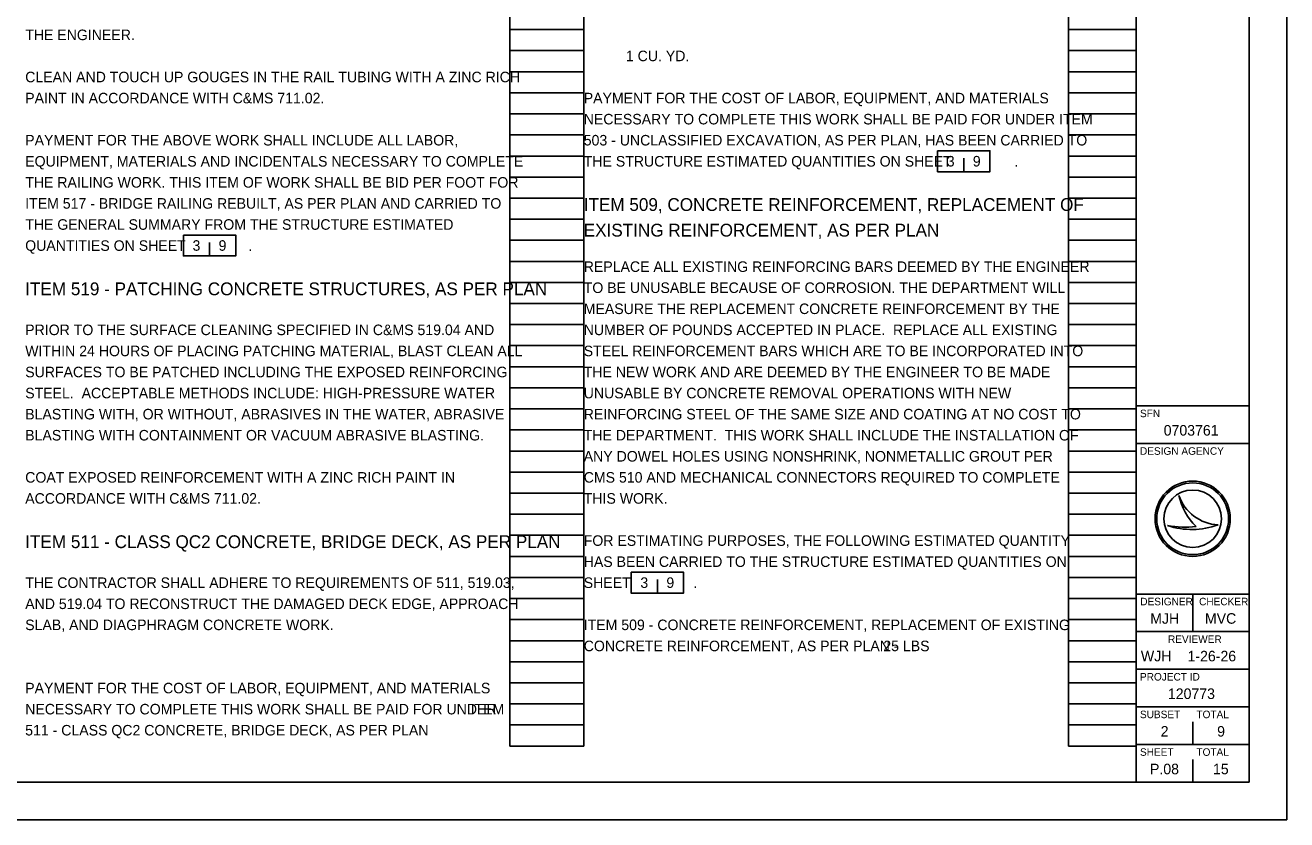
# Model space of a CAD drawing. Extents: x -16.5 to 61.9, y -20 to 22.7.
# Drawn here: x 17.24 to 34, y 0 to 10.56 of the extents above; entities that cross this region are included whole.
import ezdxf

# ---------------------------------------------------------------- set-up
doc = ezdxf.new("R2010")
doc.units = 0
for name, color, linetype in [('SH_Border', 7, 'Continuous'), ('SH_Cut_Line', 7, 'Continuous'), ('SH_Data', 7, 'Continuous'), ('SH_Text', 7, 'Continuous')]:
    doc.layers.add(name, color=color, linetype=linetype)

msp = doc.modelspace()

# ---------------------------------------------------------------- linework, layer by layer
at = {"layer": 'SH_Border'}
for p, q in [((32, 0.5), (32, 21.5)), ((32, 5.5), (33.5, 5.5)), ((32, 5), (33.5, 5)), ((32, 3), (33.5, 3)), ((32.75, 3), (32.75, 2.5)), ((32, 2.5), (33.5, 2.5)), ((32, 2), (33.5, 2)), ((32, 1.5), (33.5, 1.5)), ((32, 1), (33.5, 1))]:
    msp.add_line(p, q, dxfattribs=at)
msp.add_lwpolyline([(1.5, 21.5), (33.5, 21.5), (33.5, 0.5), (1.5, 0.5)], close=True, dxfattribs=at)
at = {"layer": 'SH_Cut_Line'}
msp.add_lwpolyline([(0, 0), (34, 0), (34, 22), (0, 22)], close=True, dxfattribs=at)
at = {"layer": 'SH_Data'}
for p, q in [((23.68, 0.98), (23.68, 21.14)), ((24.66, 0.98), (24.66, 21.14)), ((31.1, 0.98), (31.1, 21.14)), ((32, 0.98), (32, 21.14)), ((23.68, 10.5), (24.66, 10.5)), ((31.1, 10.5), (32, 10.5)), ((23.68, 10.22), (24.66, 10.22)), ((31.1, 10.22), (32, 10.22)), ((23.68, 9.94), (24.66, 9.94)), ((31.1, 9.94), (32, 9.94)), ((23.68, 9.66), (24.66, 9.66)), ((31.1, 9.66), (32, 9.66)), ((23.68, 9.38), (24.66, 9.38)), ((31.1, 9.38), (32, 9.38)), ((23.68, 9.1), (24.66, 9.1)), ((31.1, 9.1), (32, 9.1)), ((23.68, 8.82), (24.66, 8.82)), ((31.1, 8.82), (32, 8.82)), ((23.68, 8.54), (24.66, 8.54)), ((31.1, 8.54), (32, 8.54)), ((23.68, 8.26), (24.66, 8.26)), ((31.1, 8.26), (32, 8.26)), ((23.68, 7.98), (24.66, 7.98)), ((31.1, 7.98), (32, 7.98)), ((23.68, 7.7), (24.66, 7.7)), ((31.1, 7.7), (32, 7.7)), ((23.68, 7.42), (24.66, 7.42)), ((31.1, 7.42), (32, 7.42)), ((23.68, 7.14), (24.66, 7.14)), ((31.1, 7.14), (32, 7.14)), ((23.68, 6.86), (24.66, 6.86)), ((31.1, 6.86), (32, 6.86)), ((23.68, 6.58), (24.66, 6.58)), ((31.1, 6.58), (32, 6.58)), ((23.68, 6.3), (24.66, 6.3)), ((31.1, 6.3), (32, 6.3)), ((23.68, 6.02), (24.66, 6.02)), ((31.1, 6.02), (32, 6.02)), ((23.68, 5.74), (24.66, 5.74)), ((31.1, 5.74), (32, 5.74)), ((23.68, 5.46), (24.66, 5.46)), ((31.1, 5.46), (32, 5.46)), ((23.68, 5.18), (24.66, 5.18)), ((31.1, 5.18), (32, 5.18)), ((23.68, 4.9), (24.66, 4.9)), ((31.1, 4.9), (32, 4.9)), ((23.68, 4.62), (24.66, 4.62)), ((31.1, 4.62), (32, 4.62)), ((23.68, 4.34), (24.66, 4.34)), ((31.1, 4.34), (32, 4.34)), ((32.567, 4.31), (32.567, 4.31)), ((23.68, 4.06), (24.66, 4.06)), ((31.1, 4.06), (32, 4.06)), ((32.417, 3.91), (32.417, 3.91)), ((32.75, 4), (32.75, 4)), ((33.087, 3.919), (33.087, 3.919)), ((23.68, 3.78), (24.66, 3.78)), ((31.1, 3.78), (32, 3.78)), ((23.68, 3.5), (24.66, 3.5)), ((31.1, 3.5), (32, 3.5)), ((23.68, 3.22), (24.66, 3.22)), ((31.1, 3.22), (32, 3.22)), ((23.68, 2.94), (24.66, 2.94)), ((31.1, 2.94), (32, 2.94)), ((23.68, 2.66), (24.66, 2.66)), ((31.1, 2.66), (32, 2.66)), ((23.68, 2.38), (24.66, 2.38)), ((31.1, 2.38), (32, 2.38)), ((23.68, 2.1), (24.66, 2.1)), ((31.1, 2.1), (32, 2.1)), ((23.68, 1.82), (24.66, 1.82)), ((31.1, 1.82), (32, 1.82)), ((23.68, 1.54), (24.66, 1.54)), ((31.1, 1.54), (32, 1.54)), ((23.68, 1.26), (24.66, 1.26)), ((31.1, 1.26), (32, 1.26)), ((32.75, 1), (32.75, 1.3)), ((23.68, 0.98), (24.66, 0.98)), ((31.1, 0.98), (32, 0.98)), ((32.375, 0.675), (32.375, 0.675)), ((32.75, 0.5), (32.75, 0.8))]:
    msp.add_line(p, q, dxfattribs=at)
for radius in [0.5, 0.477, 0.477, 0.382]:
    msp.add_circle((32.75, 4), radius, dxfattribs=at)
for centre, radius, start, end in [((33.116, 4.498), 0.58, 198.9257, 198.9319), ((33.347, 4.47), 0.796, 191.6379, 191.6421), ((33.116, 4.498), 0.58, 198.9319, 267.1657), ((33.347, 4.47), 0.796, 191.6421, 226.0947), ((32.739, 4.87), 1.013, 251.4576, 290.0832), ((32.648, 5.154), 1.266, 259.4964, 259.4995), ((32.739, 4.87), 1.013, 251.4527, 251.4576), ((32.648, 5.154), 1.266, 259.4995, 276.6672)]:
    msp.add_arc(centre, radius, start, end, dxfattribs=at)
at = {"layer": 'SH_Text'}
for p, q in [((29.709, 8.792), (29.709, 8.612)), ((19.689, 7.672), (19.689, 7.492)), ((25.638, 3.192), (25.638, 3.012))]:
    msp.add_line(p, q, dxfattribs=at)
for points in [[(29.361, 8.89), (30.057, 8.89), (30.057, 8.612), (29.361, 8.612)], [(19.341, 7.77), (20.037, 7.77), (20.037, 7.492), (19.341, 7.492)], [(25.29, 3.29), (25.986, 3.29), (25.986, 3.012), (25.29, 3.012)]]:
    msp.add_lwpolyline(points, close=True, dxfattribs=at)

# ---------------------------------------------------------------- texts
at = {"layer": 'SH_Data'}
for s, p in [('3', (29.483, 8.681)), ('9', (29.829, 8.681)), ('3', (19.463, 7.561)), ('9', (19.809, 7.561)), ('3', (25.412, 3.081)), ('9', (25.758, 3.081))]:
    msp.add_text(s, height=0.14, rotation=0, dxfattribs=at).set_placement(p)
for s, height, p in [('SFN', 0.1, (32.05, 5.35)), ('0703761', 0.14, (32.365, 5.105)), ('DESIGN AGENCY', 0.1, (32.05, 4.85)), ('DESIGNER', 0.1, (32.054, 2.85)), ('CHECKER', 0.1, (32.835, 2.85)), ('MJH', 0.14, (32.186, 2.605)), ('MVC', 0.14, (32.913, 2.605)), ('REVIEWER', 0.1, (32.422, 2.35)), ('WJH', 0.14, (32.062, 2.105)), ('1-26-26', 0.14, (32.682, 2.105)), ('PROJECT ID', 0.1, (32.05, 1.85)), ('120773', 0.14, (32.421, 1.605)), ('SUBSET', 0.1, (32.05, 1.35)), ('TOTAL', 0.1, (32.8, 1.35)), ('2', 0.14, (32.325, 1.105)), ('9', 0.14, (33.075, 1.105)), ('SHEET', 0.1, (32.05, 0.85)), ('TOTAL', 0.1, (32.8, 0.85)), ('P.08', 0.14, (32.183, 0.605)), ('15', 0.14, (33.02, 0.605))]:
    msp.add_text(s, height=height, dxfattribs=at).set_placement(p)
at = {"layer": 'SH_Text'}
for s, height, p in [('THE ENGINEER.', 0.14, (17.24, 10.36)), ('1 CU. YD. ', 0.14, (25.22, 10.08)), ('CLEAN AND TOUCH UP GOUGES IN THE RAIL TUBING WITH A ZINC RICH ', 0.14, (17.24, 9.8)), ('PAINT IN ACCORDANCE WITH C&MS 711.02.', 0.14, (17.24, 9.52)), ('PAYMENT FOR THE COST OF LABOR, EQUIPMENT, AND MATERIALS ', 0.14, (24.66, 9.52)), ('NECESSARY TO COMPLETE THIS WORK SHALL BE PAID FOR UNDER ITEM ', 0.14, (24.66, 9.24)), ('PAYMENT FOR THE ABOVE WORK SHALL INCLUDE ALL LABOR, ', 0.14, (17.24, 8.96)), ('503 - UNCLASSIFIED EXCAVATION, AS PER PLAN, HAS BEEN CARRIED TO ', 0.14, (24.66, 8.96)), ('EQUIPMENT, MATERIALS AND INCIDENTALS NECESSARY TO COMPLETE ', 0.14, (17.24, 8.68)), ('THE STRUCTURE ESTIMATED QUANTITIES ON SHEET                .', 0.14, (24.66, 8.68)), ('THE RAILING WORK. THIS ITEM OF WORK SHALL BE BID PER FOOT FOR ', 0.14, (17.24, 8.4)), ('ITEM 517 - BRIDGE RAILING REBUILT, AS PER PLAN AND CARRIED TO ', 0.14, (17.24, 8.12)), ('ITEM 509, CONCRETE REINFORCEMENT, REPLACEMENT OF ', 0.17, (24.66, 8.09)), ('THE GENERAL SUMMARY FROM THE STRUCTURE ESTIMATED ', 0.14, (17.24, 7.84)), ('EXISTING REINFORCEMENT, AS PER PLAN', 0.17, (24.66, 7.75)), ('QUANTITIES ON SHEET                .', 0.14, (17.24, 7.56)), ('REPLACE ALL EXISTING REINFORCING BARS DEEMED BY THE ENGINEER ', 0.14, (24.66, 7.28)), ('ITEM 519 - PATCHING CONCRETE STRUCTURES, AS PER PLAN', 0.17, (17.24, 6.97)), ('TO BE UNUSABLE BECAUSE OF CORROSION. THE DEPARTMENT WILL ', 0.14, (24.66, 7)), ('MEASURE THE REPLACEMENT CONCRETE REINFORCEMENT BY THE ', 0.14, (24.66, 6.72)), ('PRIOR TO THE SURFACE CLEANING SPECIFIED IN C&MS 519.04 AND ', 0.14, (17.24, 6.44)), ('NUMBER OF POUNDS ACCEPTED IN PLACE.  REPLACE ALL EXISTING ', 0.14, (24.66, 6.44)), ('WITHIN 24 HOURS OF PLACING PATCHING MATERIAL, BLAST CLEAN ALL ', 0.14, (17.24, 6.16)), ('STEEL REINFORCEMENT BARS WHICH ARE TO BE INCORPORATED INTO ', 0.14, (24.66, 6.16)), ('SURFACES TO BE PATCHED INCLUDING THE EXPOSED REINFORCING ', 0.14, (17.24, 5.88)), ('THE NEW WORK AND ARE DEEMED BY THE ENGINEER TO BE MADE ', 0.14, (24.66, 5.88)), ('STEEL.  ACCEPTABLE METHODS INCLUDE: HIGH-PRESSURE WATER ', 0.14, (17.24, 5.6)), ('UNUSABLE BY CONCRETE REMOVAL OPERATIONS WITH NEW ', 0.14, (24.66, 5.6)), ('BLASTING WITH, OR WITHOUT, ABRASIVES IN THE WATER, ABRASIVE ', 0.14, (17.24, 5.32)), ('REINFORCING STEEL OF THE SAME SIZE AND COATING AT NO COST TO ', 0.14, (24.66, 5.32)), ('BLASTING WITH CONTAINMENT OR VACUUM ABRASIVE BLASTING.', 0.14, (17.24, 5.04)), ('THE DEPARTMENT.  THIS WORK SHALL INCLUDE THE INSTALLATION OF ', 0.14, (24.66, 5.04)), ('ANY DOWEL HOLES USING NONSHRINK, NONMETALLIC GROUT PER ', 0.14, (24.66, 4.76)), ('COAT EXPOSED REINFORCEMENT WITH A ZINC RICH PAINT IN ', 0.14, (17.24, 4.48)), ('CMS 510 AND MECHANICAL CONNECTORS REQUIRED TO COMPLETE ', 0.14, (24.66, 4.48)), ('ACCORDANCE WITH C&MS 711.02.', 0.14, (17.24, 4.2)), ('THIS WORK.', 0.14, (24.66, 4.2)), ('ITEM 511 - CLASS QC2 CONCRETE, BRIDGE DECK, AS PER PLAN', 0.17, (17.24, 3.61)), ('FOR ESTIMATING PURPOSES, THE FOLLOWING ESTIMATED QUANTITY ', 0.14, (24.66, 3.64)), ('HAS BEEN CARRIED TO THE STRUCTURE ESTIMATED QUANTITIES ON ', 0.14, (24.66, 3.36)), ('THE CONTRACTOR SHALL ADHERE TO REQUIREMENTS OF 511, 519.03,  ', 0.14, (17.24, 3.08)), ('SHEET                .', 0.14, (24.66, 3.08)), ('AND 519.04 TO RECONSTRUCT THE DAMAGED DECK EDGE, APPROACH ', 0.14, (17.24, 2.8)), ('SLAB, AND DIAGPHRAGM CONCRETE WORK.', 0.14, (17.24, 2.52)), ('ITEM 509 - CONCRETE REINFORCEMENT, REPLACEMENT OF EXISTING ', 0.14, (24.66, 2.52)), ('CONCRETE REINFORCEMENT, AS PER PLAN - ', 0.14, (24.66, 2.24)), ('25 LBS', 0.14, (28.64, 2.24)), ('PAYMENT FOR THE COST OF LABOR, EQUIPMENT, AND MATERIALS ', 0.14, (17.24, 1.68)), ('NECESSARY TO COMPLETE THIS WORK SHALL BE PAID FOR UNDER ', 0.14, (17.24, 1.4)), ('ITEM ', 0.14, (23.157, 1.4)), ('511 - CLASS QC2 CONCRETE, BRIDGE DECK, AS PER PLAN', 0.14, (17.24, 1.12))]:
    msp.add_text(s, height=height, dxfattribs=at).set_placement(p)

doc.saveas('drawing.dxf')
